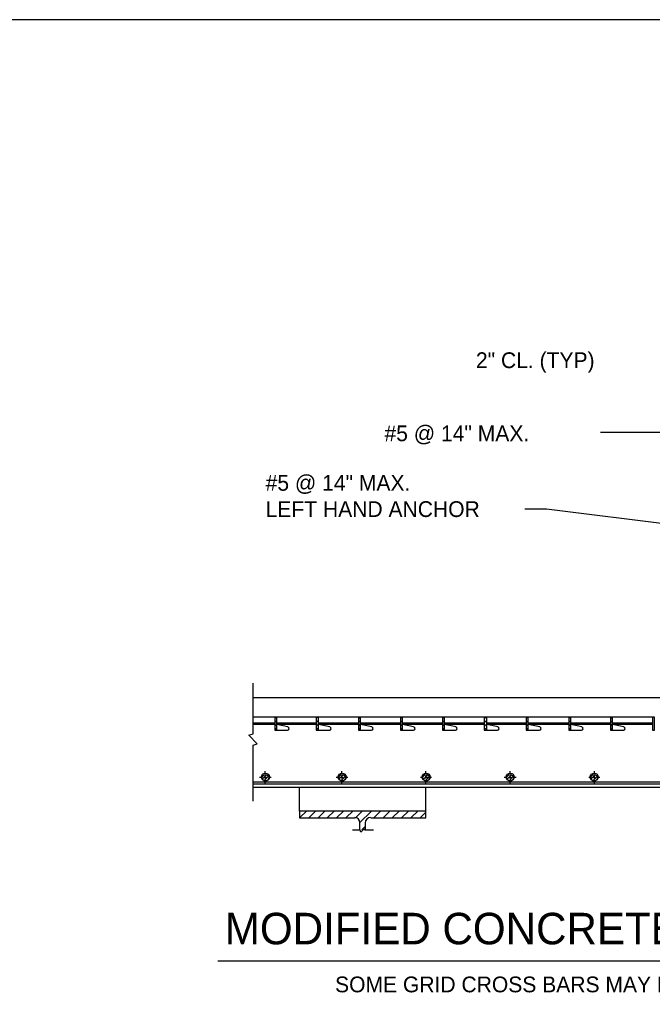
# Model space of a CAD drawing. Extents: x -24512 to -22484, y 4569 to 6351.
# Drawn here: x -23752.2 to -23631.6, y 4962.7 to 5148 of the extents above; entities that cross this region are included whole.
import ezdxf

# ---------------------------------------------------------------- set-up
doc = ezdxf.new("R2010")
doc.units = 0
for name, color, linetype in [('10', 7, 'Continuous'), ('11', 7, 'Continuous'), ('2', 7, 'Continuous'), ('4', 7, 'Continuous'), ('5', 7, 'Continuous')]:
    doc.layers.add(name, color=color, linetype=linetype)

# ---------------------------------------------------------------- blocks, each defined once
blk = doc.blocks.new('_X')
at = {"layer": '4'}
for p, q in [((63.193375, 24.416625), (63.299125, 24.522375)), ((63.193375, 24.1315), (63.3445, 24.282625)), ((63.193375, 23.846375), (63.3445, 23.9975)), ((63.193375, 23.56125), (63.3445, 23.712375))]:
    blk.add_line(p, q, dxfattribs=at)
blk = doc.blocks.new('JUQ000')
at = {"layer": '4'}
for p, q in [((71.0975, 21.771125), (71.421875, 22.095625)), ((71.237875, 21.6265), (71.566625, 21.95525))]:
    blk.add_line(p, q, dxfattribs=at)
blk = doc.blocks.new('JUQ003')
at = {"layer": '4'}
for p, q in [((89.35625, 63.69525), (89.860375, 64.19925)), ((90.069125, 63.69525), (90.573125, 64.19925)), ((90.781875, 63.69525), (91.285875, 64.19925)), ((91.49475, 63.69525), (91.99875, 64.19925)), ((92.2075, 63.69525), (92.7115, 64.19925)), ((92.920375, 63.69525), (93.424375, 64.19925)), ((93.628875, 63.691), (94.137125, 64.19925)), ((93.972625, 63.321875), (94.85, 64.19925)), ((95.05875, 63.69525), (95.56275, 64.19925)), ((95.7715, 63.69525), (96.275625, 64.19925)), ((96.484375, 63.69525), (96.988375, 64.19925)), ((97.197125, 63.69525), (97.70125, 64.19925)), ((97.91, 63.69525), (98.414, 64.19925)), ((98.62275, 63.69525), (99.014, 64.0865)), ((94.121125, 62.757625), (94.377, 63.013375))]:
    blk.add_line(p, q, dxfattribs=at)

msp = doc.modelspace()

# ---------------------------------------------------------------- linework, layer by layer
at = {"layer": '10'}
for p, q in [((-23641.51, 5069.44), (-23613.09, 5069.44)), ((-23655.92, 5054.82), (-23651.79, 5054.82)), ((-23651.79, 5054.82), (-23609.9, 5049.63)), ((-23706.48, 5003.75), (-23705.86, 5003.75)), ((-23705.61, 5003.75), (-23705.11, 5003.75)), ((-23705.36, 5004.38), (-23705.36, 5004.88)), ((-23705.36, 5003.5), (-23705.36, 5004)), ((-23704.74, 5003.75), (-23704.24, 5003.75)), ((-23691.86, 5003.75), (-23691.24, 5003.75)), ((-23690.99, 5003.75), (-23690.49, 5003.75)), ((-23690.74, 5004.38), (-23690.74, 5004.88)), ((-23690.74, 5003.5), (-23690.74, 5004)), ((-23690.11, 5003.75), (-23689.62, 5003.75)), ((-23675.78, 5003.75), (-23675.28, 5003.75)), ((-23674.9, 5003.75), (-23674.4, 5003.75)), ((-23674.78, 5004.38), (-23674.78, 5004.88)), ((-23674.78, 5003.5), (-23674.78, 5004)), ((-23674.03, 5003.75), (-23673.66, 5003.75)), ((-23659.82, 5003.75), (-23659.32, 5003.75)), ((-23658.94, 5003.75), (-23658.44, 5003.75)), ((-23658.69, 5004.38), (-23658.69, 5004.88)), ((-23658.69, 5003.5), (-23658.69, 5004)), ((-23658.07, 5003.75), (-23657.57, 5003.75)), ((-23643.73, 5003.75), (-23643.23, 5003.75)), ((-23642.98, 5003.75), (-23642.48, 5003.75)), ((-23642.61, 5004.38), (-23642.61, 5004.88)), ((-23642.61, 5003.5), (-23642.61, 5004)), ((-23642.11, 5003.75), (-23641.61, 5003.75)), ((-23705.36, 5002.63), (-23705.36, 5003.13)), ((-23690.74, 5002.63), (-23690.74, 5003.13)), ((-23674.78, 5002.63), (-23674.78, 5003.13)), ((-23658.69, 5002.63), (-23658.69, 5003.13)), ((-23642.61, 5002.63), (-23642.61, 5003.13))]:
    msp.add_line(p, q, dxfattribs=at)
at = {"layer": '11'}
msp.add_line((-23478.7, 4968.7), (-23714.4, 4968.7), dxfattribs=at)
at = {"layer": '2'}
msp.add_line((-24137.79, 5148.04), (-23353.75, 5148.04), dxfattribs=at)
at = {"layer": '5'}
for p, q in [((-23575.15, 5018.88), (-23707.59, 5018.88)), ((-23703.53, 5015.17), (-23707.63, 5015.17)), ((-23695.68, 5015.17), (-23703.16, 5015.17)), ((-23687.57, 5015.17), (-23695.18, 5015.17)), ((-23679.59, 5015.17), (-23687.2, 5015.17)), ((-23671.61, 5015.17), (-23679.22, 5015.17)), ((-23663.63, 5015.17), (-23671.24, 5015.17)), ((-23655.65, 5015.17), (-23663.13, 5015.17)), ((-23647.55, 5015.17), (-23655.28, 5015.17)), ((-23639.57, 5015.17), (-23647.17, 5015.17)), ((-23631.59, 5015.17), (-23639.19, 5015.17)), ((-23703.53, 5014.05), (-23707.63, 5014.05)), ((-23703.53, 5013.8), (-23707.63, 5013.8)), ((-23695.68, 5014.05), (-23703.16, 5014.05)), ((-23695.68, 5013.8), (-23703.16, 5013.8)), ((-23701.04, 5013.3), (-23703.16, 5013.8)), ((-23687.57, 5014.05), (-23695.18, 5014.05)), ((-23687.57, 5013.8), (-23695.18, 5013.8)), ((-23693.06, 5013.3), (-23695.18, 5013.8)), ((-23679.59, 5014.05), (-23687.2, 5014.05)), ((-23679.59, 5013.8), (-23687.2, 5013.8)), ((-23685.08, 5013.3), (-23687.2, 5013.8)), ((-23671.61, 5014.05), (-23679.22, 5014.05)), ((-23671.61, 5013.8), (-23679.22, 5013.8)), ((-23677.1, 5013.3), (-23679.22, 5013.8)), ((-23663.63, 5014.05), (-23671.24, 5014.05)), ((-23663.63, 5013.8), (-23671.24, 5013.8)), ((-23668.99, 5013.3), (-23671.24, 5013.8)), ((-23655.65, 5014.05), (-23663.13, 5014.05)), ((-23655.65, 5013.8), (-23663.13, 5013.8)), ((-23661.01, 5013.3), (-23663.13, 5013.8)), ((-23647.55, 5014.05), (-23655.28, 5014.05)), ((-23647.55, 5013.8), (-23655.28, 5013.8)), ((-23653.03, 5013.3), (-23655.28, 5013.8)), ((-23639.57, 5014.05), (-23647.17, 5014.05)), ((-23639.57, 5013.8), (-23647.17, 5013.8)), ((-23645.05, 5013.3), (-23647.17, 5013.8)), ((-23631.59, 5014.05), (-23639.19, 5014.05)), ((-23631.59, 5013.8), (-23639.19, 5013.8)), ((-23637.07, 5013.3), (-23639.19, 5013.8)), ((-23703.16, 5012.68), (-23701.16, 5012.68)), ((-23695.18, 5012.68), (-23693.06, 5012.68)), ((-23687.2, 5012.68), (-23685.2, 5012.68)), ((-23679.22, 5012.68), (-23677.1, 5012.68)), ((-23671.24, 5012.68), (-23669.12, 5012.68)), ((-23663.13, 5012.68), (-23661.14, 5012.68)), ((-23655.28, 5012.68), (-23653.16, 5012.68)), ((-23647.17, 5012.68), (-23645.18, 5012.68)), ((-23639.19, 5012.68), (-23637.07, 5012.68)), ((-23597.22, 5002.76), (-23707.59, 5002.76)), ((-23597.22, 5002.38), (-23707.59, 5002.38)), ((-23597.22, 5001.76), (-23707.59, 5001.76)), ((-23698.84, 4997.27), (-23698.84, 5001.76)), ((-23674.78, 4997.27), (-23674.78, 5001.76)), ((-23674.78, 4997.27), (-23698.84, 4997.27)), ((-23698.84, 4997.27), (-23698.84, 4996.02)), ((-23674.78, 4996.02), (-23674.78, 4997.27)), ((-23698.84, 4996.02), (-23688.24, 4996.02)), ((-23687.37, 4995.03), (-23687.37, 4993.65)), ((-23686.25, 4993.65), (-23686.25, 4995.03)), ((-23685.25, 4996.02), (-23674.78, 4996.02)), ((-23687.37, 4993.65), (-23688.74, 4993.65)), ((-23684.75, 4993.65), (-23686.25, 4993.65))]:
    msp.add_line(p, q, dxfattribs=at)
for points in [[(-23707.63, 4999.19), (-23707.63, 5009.85), (-23706.88, 5010.1), (-23708.5, 5011.72), (-23707.63, 5011.97), (-23707.63, 5021.65)], [(-23686.25, 4993.65), (-23686.37, 4993.65), (-23686.5, 4993.9), (-23687.12, 4993.28), (-23687.25, 4993.65), (-23687.37, 4993.65)]]:
    msp.add_lwpolyline(points, dxfattribs=at)
for points in [[(-23703.53, 5015.17), (-23703.53, 5012.68), (-23703.16, 5012.68), (-23703.16, 5015.17)], [(-23695.68, 5015.17), (-23695.68, 5012.68), (-23695.18, 5012.68), (-23695.18, 5015.17)], [(-23687.57, 5015.17), (-23687.57, 5012.68), (-23687.2, 5012.68), (-23687.2, 5015.17)], [(-23679.59, 5015.17), (-23679.59, 5012.68), (-23679.22, 5012.68), (-23679.22, 5015.17)], [(-23671.61, 5015.17), (-23671.61, 5012.68), (-23671.24, 5012.68), (-23671.24, 5015.17)], [(-23663.63, 5015.17), (-23663.63, 5012.68), (-23663.13, 5012.68), (-23663.13, 5015.17)], [(-23655.65, 5015.17), (-23655.65, 5012.68), (-23655.28, 5012.68), (-23655.28, 5015.17)], [(-23647.55, 5015.17), (-23647.55, 5012.68), (-23647.17, 5012.68), (-23647.17, 5015.17)], [(-23639.57, 5015.17), (-23639.57, 5012.68), (-23639.19, 5012.68), (-23639.19, 5015.17)], [(-23631.59, 5015.17), (-23631.59, 5012.68), (-23631.21, 5012.68), (-23631.21, 5015.17)]]:
    msp.add_lwpolyline(points, close=True, dxfattribs=at)
for centre, radius in [((-23705.32, 5003.77), 0.75), ((-23705.32, 5003.64), 0.625), ((-23690.7, 5003.77), 0.75), ((-23690.7, 5003.64), 0.625), ((-23674.7, 5003.77), 0.75), ((-23674.7, 5003.64), 0.625), ((-23658.69, 5003.77), 0.75), ((-23658.69, 5003.64), 0.625), ((-23642.69, 5003.77), 0.75), ((-23642.69, 5003.64), 0.625)]:
    msp.add_circle(centre, radius, dxfattribs=at)
for centre, radius, start, end in [((-23701.13, 5012.99), 0.305, 271.249, 76.5605), ((-23693.13, 5012.99), 0.305, 271.249, 76.5605), ((-23685.13, 5012.99), 0.305, 271.249, 76.5605), ((-23677.13, 5012.99), 0.305, 271.249, 76.5605), ((-23669.13, 5012.99), 0.305, 271.249, 76.5605), ((-23661.12, 5012.99), 0.305, 271.249, 76.5605), ((-23653.12, 5012.99), 0.305, 271.249, 76.5605), ((-23645.12, 5012.99), 0.305, 271.249, 76.5605), ((-23637.12, 5012.99), 0.305, 271.249, 76.5605), ((-23688.31, 4995.06), 1, 0, 90), ((-23685.31, 4995.06), 1, 90, 180)]:
    msp.add_arc(centre, radius, start, end, dxfattribs=at)

# ---------------------------------------------------------------- block references
at = {"layer": '4', "xscale": 2.4803976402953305, "yscale": 2.4803976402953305}
for name, p in [('_X', (-23860.28, 4954.33)), ('_X', (-23852.41, 4954.33)), ('_X', (-23844.3, 4954.33)), ('_X', (-23836.32, 4954.33)), ('_X', (-23828.34, 4954.33)), ('_X', (-23820.36, 4954.33)), ('_X', (-23812.38, 4954.33)), ('_X', (-23804.28, 4954.33)), ('_X', (-23796.3, 4954.33)), ('JUQ000', (-23882.29, 4949.39)), ('JUQ000', (-23867.67, 4949.39)), ('JUQ000', (-23851.58, 4949.39)), ('JUQ000', (-23835.62, 4949.39)), ('JUQ000', (-23819.66, 4949.39)), ('JUQ003', (-23920.41, 4838.04))]:
    msp.add_blockref(name, p, dxfattribs=at)

# ---------------------------------------------------------------- texts
at = {"layer": '10'}
for s, p in [('2" CL. (TYP)', (-23665.22, 5081.65)), ('#5 @ 14" MAX.', (-23682.64, 5067.72)), ('#5 @ 14" MAX.', (-23705.28, 5058.29)), ('LEFT HAND ANCHOR', (-23705.28, 5053.29)), ('SOME GRID CROSS BARS MAY BE OMITTED TO FACILITATE REBAR PLACEMENT', (-23692.05, 4962.77))]:
    msp.add_text(s, height=3, dxfattribs=at).set_placement(p)
at = {"layer": '11'}
msp.add_text('MODIFIED CONCRETE MEDIAN BARRIER DETAIL', height=6.0008, dxfattribs=at).set_placement((-23713.06, 4971.91))

doc.saveas('drawing.dxf')
